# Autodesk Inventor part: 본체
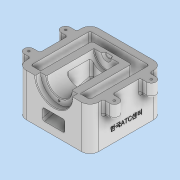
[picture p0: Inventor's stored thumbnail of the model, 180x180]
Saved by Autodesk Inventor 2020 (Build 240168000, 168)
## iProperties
Created: 2022-03
Part Number: 본체
Material: 일반
Document SubType Name: Modeling
Designer: Administrator
Density: 1 g/cm^3
Appearance: 기본값
Author: Administrator
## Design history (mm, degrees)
sketch "스케치1"
  geometry: L1 (55, 55)-(-55, 55); L2 (-55, 55)-(-55, -55); L3 (-55, -55)-(55, -55); L4 (55, -55)-(55, 55); L5 (55, 55)-(-55, -55); L6 (-55, 55)-(55, -55); 1 further point
  constraints: 12 end point, 2 midpoint, 2 parallel, 1 horizontal, 1 perpendicular
  dimensions: "d0" = 110 distance of L3.end L1.start; "d1" = 110 distance of L1.start L1.end
extrude "돌출1" new body sketch "스케치1" distance "d2" = 65; taper "d3" = 0 deg
sketch "스케치2"
  geometry: L1 (45, 65)-(45, 0); L2 (-55, 65)-(55, 65) reference; L3 (55, 0)-(55, 65) reference; L4 (-55, 0)-(55, 0) reference; L5 (33, 65)-(33, 30); L6 (33, 30)-(-45, 9.1); L7 (-45, 9.1)-(-45, 0); L8 (-55, 11.597)-(19, 31.425); L9 (19, 31.425)-(19, 65); L10 (-19, 65)-(-19, 38.843); L11 (-19, 38.843)-(-55, 29.197); L12 (-55, 0)-(-55, 65) reference; 2 further points
  constraints: 16 end point, 7 point on line, 3 vertical
  dimensions: "d4" = 22 distance between parallel lines of L3 L5; "d5" = 10 distance between parallel lines of L3 L1; "d6" = 30 distance from line of L4 L5.end; "d7" = 75 deg angle of L6 L5; "d8" = 10 distance from line of L4.start L7; "d29" = 5 distance between parallel lines of L6 L8; "d30" = 17 distance between parallel lines of L8 L11; "d37" = 36 distance between parallel lines of L12 L10; "d38" = 38 distance between parallel lines of L9 L10
sketch "스케치3"
  geometry: L1 (-55, 55)-(-55, -55) reference; L2 (55, -55)-(55, 55) reference; L3 (-55, 0)-(55, 0); L4 (55, 28)-(47, 28); L5 (47, 28)-(47, 19); L6 (47, 19)-(-25, 19); L7 (-25, 19)-(-25, 7.5); L8 (-25, 7.5)-(-29, 5.191); L9 (-29, 5.191)-(-29, 0); 1 further point
  constraints: 14 end point, 3 perpendicular, 2 midpoint, 2 point on line, 1 horizontal, 1 vertical
  dimensions: "d9" = 56 diameter of L4 L3; "d11" = 38 diameter of L6 L3; "d12" = 8 distance of L4.start L4.end; "d13" = 72 distance of L5.end L6.end; "d14" = 30 deg angle of L3 L8; "d15" = 4 distance between parallel lines of L7 L9; "d61" = 15 diameter of L7.end L3
revolve "회전1" sketch "스케치3" stored, may be unused: angle "d17" = 90 deg
sketch "스케치4"
  geometry: L1 (-35, -65)-(-35, -55); L2 (-21, -65)-(-21, -55); L3 (-55, -55)-(55, -55) reference; L4 (-55, 55)-(-55, -55) reference; A1 r 7 centre (-28, -65) between (-35, -65) and (-21, -65); 1 further point
  constraints: 4 end point, 2 point on circle, 2 point on line, 2 vertical, 1 centre point
  dimensions: "d18" = 14 diameter of A1; "d19" = 65 vertical distance of point (0, 0) A1.centre; "d42" = 27 distance from line of A1.centre L4
extrude "돌출2" join sketch "스케치4" distance "d20" = 20; taper "d21" = 0 deg
sketch "스케치5"
  geometry: A1 r 7 centre (-28, -65) between (-35, -65) and (-21, -65) reference; 2 further points
  constraints: 1 coincident
hole "구멍1" sketch "스케치5" at (-28, -65) diameter "d22" = 3.242; stored, may be unused: countersink angle "d26" = 90 deg, drill point angle "d28" = 118 deg; dims "d23" = 9, "d24" = 18, "d25" = 2, "d27" = 11
extrude "돌출3" cut sketch "스케치2" stored distance "d32" = 34; taper "d33" = 0 deg
extrude "돌출4" cut sketch "스케치2" stored distance "d34" = 90; taper "d35" = 0 deg
sketch "스케치6"
  geometry: L1 (-45, -45)-(45, -45) reference; L2 (-45, -30)-(45, -30); L3 (45, -30)-(45, -45); L4 (-45, -45)-(-45, 45) reference; 1 further point
  constraints: 4 end point, 1 parallel, 1 point on line, 1 vertical
  dimensions: "d36" = 15 distance between parallel lines of L1 L2
extrude "돌출5" cut sketch "스케치6" distance "d39" = 90; taper "d40" = 0 deg
fillet "모깎기1" dims "d41" = 1
fillet "모깎기2" dims "d43" = 13
fillet "모깎기3" dims "d44" = 3
sketch "스케치7"
  geometry: A1 r 28 centre (0, -19) between (0, -47) and (0, 9) reference; 2 further points
  constraints: 1 horizontal alignment
  dimensions: "d45" = 23 distance of A1.centre point (23, -19)
hole "구멍2" sketch "스케치7" at (23, -19) diameter "d46" = 3.242; stored, may be unused: countersink angle "d50" = 90 deg, drill point angle "d52" = 118 deg; dims "d47" = 9, "d48" = 18, "d49" = 2, "d51" = 11
fillet "모깎기4" dims "d53" = 3
chamfer "모따기1" distance "d54" = 1; stored, may be unused: second distance "d55" = 2, angle "d56" = 45 deg
sketch "스케치8"
  geometry: L1 (97, -65)-(97, 0) reference; 2 further points
  constraints: 1 other
  dimensions: "d57" = 20 distance of point (42, 0) point (42, -20); "d58" = 55 distance from line of point (42, -20) L1
feature "엠보싱1" sketch "스케치8" dims "d0" = 110, "d1" = 110, "d59" = 0.5, "d60" = 0
fillet "모깎기5" dims "d62" = 3
fillet "모깎기6" dims "d63" = 3
fillet "모깎기7" dims "d64" = 3
node "솔리드1"
mirror "미러1"
mirror "미러2"
mirror "미러3"
feature "A9D066F2-1C7D-4E18-AEED-F7BC21143FA4" dims "d22" = 3.242, "d23" = 9, "d24" = 18, "d25" = 2, "d26" = 90 deg, "d27" = 11, "d28" = 118 deg
